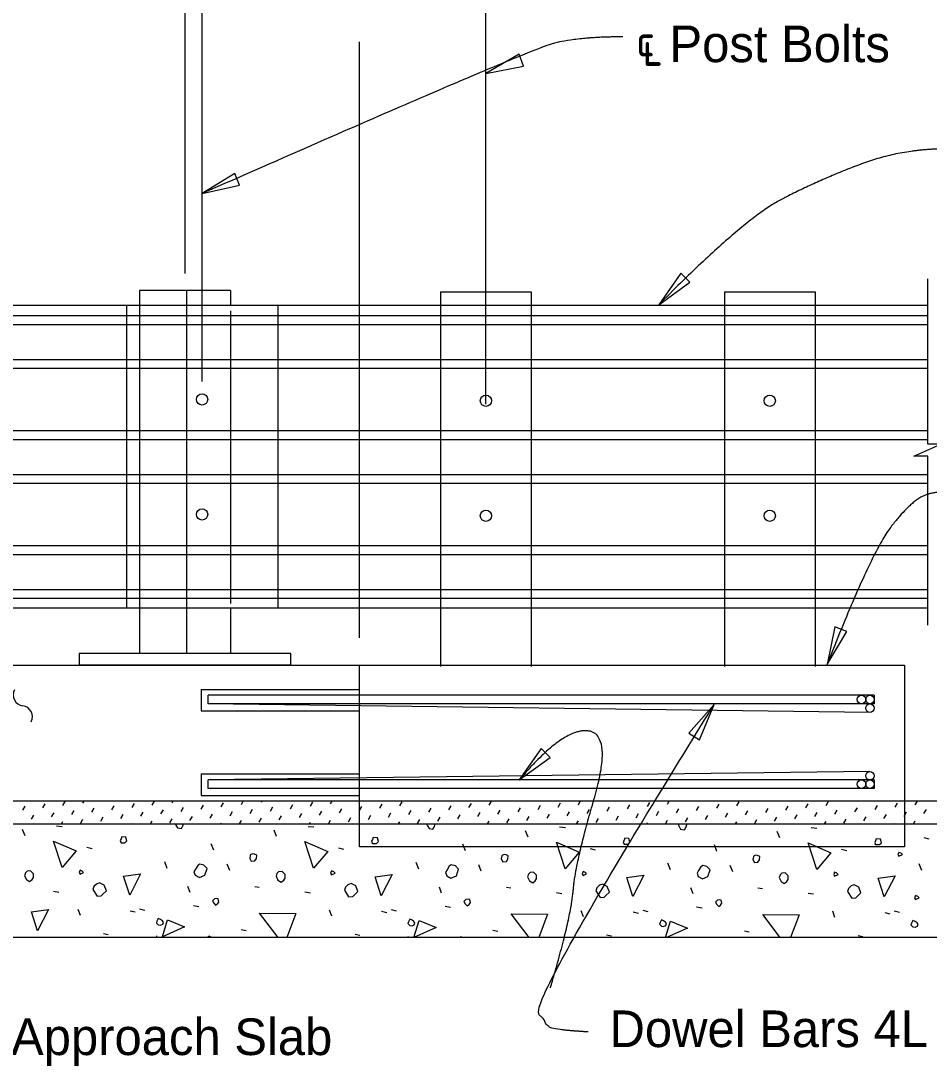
# Model space of a CAD drawing. Extents: x 0 to 41.1, y 0 to 25.9.
# Drawn here: x 31.99 to 36.99, y 5.25 to 11.01 of the extents above; entities that cross this region are included whole.
import ezdxf

# ---------------------------------------------------------------- set-up
doc = ezdxf.new("R2010")
doc.units = 0
for name, color, linetype in [('Dimension', 7, 'Continuous'), ('ExistSuperStruct', 7, 'Continuous'), ('Miscellaneous', 7, 'Continuous'), ('Rebar', 7, 'Continuous'), ('SteelMisc', 7, 'Continuous'), ('SteelMisc_h', 7, 'Continuous'), ('SubStrConc', 7, 'Continuous'), ('SubStrConc_h', 7, 'Continuous'), ('TextStructures', 7, 'Continuous')]:
    doc.layers.add(name, color=color, linetype=linetype)

msp = doc.modelspace()

# ---------------------------------------------------------------- linework, layer by layer
at = {"layer": 'Dimension'}
msp.add_line((33.8558, 7.6097), (33.8558, 10.8914), dxfattribs=at)
for points in [[(34.5515, 10.7168), (34.7588, 10.7573), (34.7339, 10.8233)], [(32.989, 10.0554), (33.1953, 10.1006), (33.1689, 10.1661)], [(35.5032, 9.4435), (35.6748, 9.5667), (35.6246, 9.6163)], [(36.43, 7.4629), (36.5385, 7.6441), (36.4727, 7.6697)], [(35.8076, 7.2429), (35.668, 7.0845), (35.7279, 7.0473)], [(34.7347, 6.8272), (34.9058, 6.9511), (34.8554, 7.0005)]]:
    msp.add_lwpolyline(points, close=True, dxfattribs=at)
msp.add_lwpolyline([(36.9839, 7.6788), (36.9839, 8.6104), (36.9064, 8.6104), (37.0564, 8.6766), (36.9839, 8.6766), (36.9839, 9.5855)], dxfattribs=at)
for centre, start, end in [((32.0093, 7.2949), 151.52667, 263.25389), ((31.9952, 7.1765), 331.52667, 83.25389)]:
    msp.add_arc(centre, 0.0596, start, end, dxfattribs=at)
for points in [[(35.3048, 10.9179), (35.0595, 10.9179), (34.7744, 10.8416), (32.989, 10.0554)], [(37.0881, 10.3011), (36.8373, 10.3011), (36.3859, 10.1306), (35.9697, 9.9149), (35.5032, 9.4435)], [(37.2746, 8.4245), (37.0591, 8.4245), (36.8965, 8.3714), (36.6668, 8.0709), (36.43, 7.4629)], [(35.1149, 5.4399), (34.9417, 5.4505), (34.8781, 5.4752), (34.8109, 5.6343), (35.8076, 7.2429)], [(34.9069, 5.6836), (35.0194, 6.0656), (35.045, 6.3745), (35.2517, 7.0806), (34.9766, 7.1138), (34.7347, 6.8272)]]:
    msp.add_open_spline(points, degree=2, dxfattribs=at)
at = {"layer": 'ExistSuperStruct'}
for p, q in [((26.6139, 7.4599), (34.561, 7.4599)), ((32.9842, 7.3261), (33.8562, 7.3261)), ((32.9842, 7.3261), (32.9842, 7.2083)), ((32.9842, 7.2083), (33.8562, 7.2083)), ((32.9842, 6.8601), (33.8562, 6.8601)), ((32.9842, 6.8601), (32.9842, 6.7423)), ((32.9842, 6.7423), (33.8562, 6.7423)), ((37.3622, 6.71), (26.6139, 6.71)), ((26.6139, 6.585), (37.3622, 6.585)), ((37.3622, 5.9599), (31.8338, 5.9599))]:
    msp.add_line(p, q, dxfattribs=at)
at = {"layer": 'Miscellaneous'}
for p, q in [((32.989, 9.0213), (32.989, 14.0792)), ((32.8952, 9.6154), (32.8952, 11.9805)), ((34.5515, 8.8961), (34.5515, 11.264)), ((34.3015, 9.5149), (34.3015, 7.4525)), ((34.3015, 9.5149), (34.8015, 9.5149)), ((34.8015, 9.5149), (34.8015, 7.4525)), ((35.864, 9.5149), (35.864, 7.4525)), ((35.864, 9.5149), (36.364, 9.5149)), ((36.364, 9.5149), (36.364, 7.4525)), ((32.5722, 9.4391), (32.5722, 7.7725)), ((33.4055, 9.4391), (33.4055, 7.7725)), ((32.5722, 9.3835), (36.9839, 9.3835)), ((32.5722, 9.3352), (36.9839, 9.3352)), ((32.5722, 9.1424), (36.9839, 9.1424)), ((32.5722, 9.0942), (36.9839, 9.0942)), ((32.5722, 8.7502), (36.9839, 8.7502)), ((32.5722, 8.702), (36.9839, 8.702)), ((32.5722, 8.5092), (36.9839, 8.5092)), ((32.5722, 8.4611), (36.9839, 8.4611)), ((32.5722, 8.1171), (36.9839, 8.1171)), ((32.5722, 8.0689), (36.9839, 8.0689)), ((32.5722, 7.8761), (36.9839, 7.8761)), ((32.5722, 7.8278), (36.9839, 7.8278)), ((32.0015, 6.6601), (32.0144, 6.6825)), ((32.1121, 6.6731), (32.1251, 6.6955)), ((32.2227, 6.686), (32.2357, 6.7084)), ((32.3334, 6.699), (32.3398, 6.71)), ((32.4928, 6.6631), (32.5058, 6.6855)), ((32.6035, 6.6761), (32.6164, 6.6985)), ((32.7141, 6.689), (32.7263, 6.71)), ((32.8247, 6.702), (32.8294, 6.71)), ((32.8736, 6.6532), (32.8865, 6.6756)), ((32.9842, 6.6661), (32.9972, 6.6885)), ((33.0948, 6.6791), (33.1078, 6.7015)), ((33.2055, 6.6921), (33.2159, 6.71)), ((33.3161, 6.705), (33.319, 6.71)), ((33.3649, 6.6562), (33.3779, 6.6786)), ((33.4756, 6.6692), (33.4885, 6.6916)), ((33.5862, 6.6821), (33.5992, 6.7045)), ((33.6968, 6.6951), (33.7055, 6.71)), ((33.8075, 6.7081), (33.8086, 6.71)), ((33.8563, 6.6592), (33.8693, 6.6816)), ((33.9669, 6.6722), (33.9799, 6.6946)), ((34.0776, 6.6851), (34.0905, 6.7075)), ((34.3477, 6.6622), (34.3606, 6.6846)), ((34.4583, 6.6752), (34.4713, 6.6976)), ((34.5689, 6.6882), (34.5816, 6.71)), ((34.7284, 6.6523), (34.7414, 6.6747)), ((34.839, 6.6653), (34.852, 6.6876)), ((34.9497, 6.6782), (34.9626, 6.7006)), ((35.0603, 6.6912), (35.0712, 6.71)), ((35.2198, 6.6553), (35.2327, 6.6777)), ((35.3304, 6.6683), (35.3434, 6.6907)), ((35.441, 6.6812), (35.454, 6.7036)), ((35.5517, 6.6942), (35.5608, 6.71)), ((35.7111, 6.6583), (35.7241, 6.6807)), ((35.8218, 6.6713), (35.8347, 6.6937)), ((35.9324, 6.6843), (35.9454, 6.7067)), ((36.2025, 6.6614), (36.2155, 6.6837)), ((36.3131, 6.6743), (36.3261, 6.6967)), ((36.4238, 6.6873), (36.4367, 6.7097)), ((36.6939, 6.6644), (36.7068, 6.6868)), ((36.8045, 6.6773), (36.8175, 6.6997)), ((36.9151, 6.6903), (36.9266, 6.71)), ((32.0503, 6.6113), (32.0633, 6.6337)), ((32.1609, 6.6242), (32.1739, 6.6466)), ((32.2716, 6.6372), (32.2845, 6.6596)), ((32.3822, 6.6502), (32.3952, 6.6725)), ((32.431, 6.6013), (32.444, 6.6237)), ((32.5417, 6.6143), (32.5546, 6.6367)), ((32.6523, 6.6272), (32.6653, 6.6496)), ((32.7629, 6.6402), (32.7759, 6.6626)), ((32.9224, 6.6043), (32.9354, 6.6267)), ((33.033, 6.6173), (33.046, 6.6397)), ((33.1437, 6.6303), (33.1566, 6.6527)), ((33.2543, 6.6432), (33.2673, 6.6656)), ((33.3031, 6.5944), (33.3161, 6.6168)), ((33.4138, 6.6074), (33.4267, 6.6298)), ((33.5244, 6.6203), (33.5374, 6.6427)), ((33.635, 6.6333), (33.648, 6.6557)), ((33.7457, 6.6463), (33.7586, 6.6686)), ((33.7945, 6.5974), (33.8075, 6.6198)), ((33.9051, 6.6104), (33.9181, 6.6328)), ((34.0158, 6.6233), (34.0287, 6.6457)), ((34.1264, 6.6363), (34.1394, 6.6587)), ((34.237, 6.6493), (34.25, 6.6717)), ((34.2859, 6.6004), (34.2988, 6.6228)), ((34.3965, 6.6134), (34.4095, 6.6358)), ((34.5071, 6.6264), (34.5201, 6.6488)), ((34.6178, 6.6393), (34.6307, 6.6617)), ((34.7772, 6.6035), (34.7902, 6.6258)), ((34.8879, 6.6164), (34.9008, 6.6388)), ((34.9985, 6.6294), (35.0115, 6.6518)), ((35.1091, 6.6423), (35.1221, 6.6647)), ((35.2686, 6.6065), (35.2816, 6.6289)), ((35.3792, 6.6194), (35.3922, 6.6418)), ((35.4899, 6.6324), (35.5028, 6.6548)), ((35.6005, 6.6454), (35.6135, 6.6678)), ((35.6493, 6.5965), (35.6623, 6.6189)), ((35.76, 6.6095), (35.7729, 6.6319)), ((35.8706, 6.6225), (35.8836, 6.6449)), ((35.9812, 6.6354), (35.9942, 6.6578)), ((36.0919, 6.6484), (36.1048, 6.6708)), ((36.1407, 6.5996), (36.1537, 6.6219)), ((36.2513, 6.6125), (36.2643, 6.6349)), ((36.362, 6.6255), (36.3749, 6.6479)), ((36.4726, 6.6384), (36.4856, 6.6608)), ((36.5832, 6.6514), (36.5962, 6.6738)), ((36.6321, 6.6026), (36.645, 6.625)), ((36.7427, 6.6155), (36.7557, 6.6379)), ((36.8533, 6.6285), (36.8663, 6.6509)), ((36.963, 6.6428), (36.976, 6.6652)), ((32.1875, 6.5755), (32.2193, 6.5719)), ((32.2153, 6.585), (32.2227, 6.5978)), ((32.3204, 6.5884), (32.3334, 6.6108)), ((32.6018, 6.585), (32.6035, 6.5878)), ((32.7049, 6.585), (32.7141, 6.6008)), ((32.8118, 6.5914), (32.8247, 6.6138)), ((33.0914, 6.585), (33.0948, 6.5909)), ((33.1946, 6.585), (33.2055, 6.6038)), ((33.5722, 6.5719), (33.604, 6.5684)), ((33.581, 6.585), (33.5862, 6.5939)), ((33.6842, 6.585), (33.6968, 6.6068)), ((34.0707, 6.585), (34.0776, 6.5969)), ((34.1752, 6.5875), (34.1882, 6.6099)), ((34.4572, 6.585), (34.4583, 6.587)), ((34.5603, 6.585), (34.5689, 6.5999)), ((34.6666, 6.5905), (34.6796, 6.6129)), ((34.9468, 6.585), (34.9497, 6.59)), ((34.9569, 6.5684), (34.9887, 6.5649)), ((35.0499, 6.585), (35.0603, 6.6029)), ((35.158, 6.5935), (35.1709, 6.6159)), ((35.4364, 6.585), (35.441, 6.593)), ((35.5395, 6.585), (35.5517, 6.606)), ((35.926, 6.585), (35.9324, 6.596)), ((36.0301, 6.5866), (36.043, 6.609)), ((36.3125, 6.585), (36.3131, 6.5861)), ((36.3416, 6.5649), (36.3734, 6.5613)), ((36.4156, 6.585), (36.4238, 6.599)), ((36.5214, 6.5896), (36.5344, 6.612)), ((36.8021, 6.585), (36.8045, 6.5891)), ((36.9052, 6.585), (36.9151, 6.6021)), ((32.0149, 6.5195), (32.0008, 6.5549)), ((33.3996, 6.516), (33.3854, 6.5513)), ((34.7843, 6.5124), (34.7701, 6.5478)), ((36.1689, 6.5089), (36.1548, 6.5443)), ((36.9615, 6.5097), (36.9898, 6.5026)), ((32.3555, 6.457), (32.3837, 6.4499)), ((33.0537, 6.4411), (33.0396, 6.4765)), ((33.7401, 6.4535), (33.7684, 6.4464)), ((34.4384, 6.4376), (34.4243, 6.4729)), ((35.1248, 6.4499), (35.1531, 6.4429)), ((35.8231, 6.434), (35.8089, 6.4694)), ((36.5095, 6.4464), (36.5378, 6.4393)), ((32.7974, 6.3403), (32.7833, 6.3757)), ((33.1415, 6.3286), (33.1274, 6.364)), ((34.1821, 6.3368), (34.1679, 6.3722)), ((34.5262, 6.3251), (34.512, 6.3604)), ((35.5668, 6.3333), (35.5526, 6.3686)), ((35.9109, 6.3215), (35.8967, 6.3569)), ((36.9514, 6.3297), (36.9373, 6.3651)), ((32.1705, 6.2155), (32.2005, 6.2102)), ((32.9229, 6.2078), (32.9105, 6.2414)), ((33.2794, 6.2402), (33.3041, 6.2367)), ((34.3076, 6.2042), (34.2952, 6.2378)), ((34.6641, 6.2367), (34.6888, 6.2331)), ((35.6923, 6.2007), (35.6799, 6.2343)), ((36.0487, 6.2331), (36.0735, 6.2296)), ((33.5552, 6.2119), (33.5852, 6.2066)), ((34.9398, 6.2084), (34.9699, 6.2031)), ((36.3245, 6.2049), (36.3546, 6.1996)), ((32.319, 6.0811), (32.3066, 6.1147)), ((32.593, 6.1076), (32.6213, 6.1006)), ((32.6454, 6.1176), (32.6737, 6.1105)), ((32.9417, 6.1359), (32.9718, 6.1306)), ((33.7036, 6.0776), (33.6913, 6.1112)), ((33.9776, 6.1041), (34.0059, 6.097)), ((34.0301, 6.1141), (34.0583, 6.107)), ((34.3264, 6.1324), (34.3565, 6.1271)), ((35.0883, 6.074), (35.0759, 6.1076)), ((35.3623, 6.1006), (35.3906, 6.0935)), ((35.4147, 6.1105), (35.443, 6.1035)), ((35.7111, 6.1288), (35.7411, 6.1235)), ((36.473, 6.0705), (36.4606, 6.1041)), ((36.7994, 6.107), (36.8277, 6.0999)), ((36.747, 6.097), (36.7753, 6.09)), ((33.2051, 6.0033), (33.2317, 5.998)), ((34.5898, 5.9998), (34.6163, 5.9945)), ((35.9745, 5.9963), (36.001, 5.991)), ((32.4462, 5.9821), (32.4728, 5.9768)), ((32.7423, 5.9599), (32.7391, 5.9686)), ((33.8309, 5.9786), (33.8574, 5.9733)), ((34.1256, 5.9599), (34.1237, 5.9651)), ((35.2156, 5.975), (35.2421, 5.9697)), ((35.509, 5.9599), (35.5084, 5.9615)), ((36.6003, 5.9715), (36.6268, 5.9662))]:
    msp.add_line(p, q, dxfattribs=at)
for points in [[(32.8422, 6.585), (32.8451, 6.579)], [(32.8451, 6.579), (32.854, 6.5631), (32.8752, 6.5596), (32.884, 6.5755), (32.8864, 6.585)], [(34.2271, 6.585), (34.2263, 6.5825), (34.2298, 6.5755)], [(34.2298, 6.5755), (34.2387, 6.5596), (34.2599, 6.556), (34.2687, 6.5719), (34.272, 6.585)], [(35.6129, 6.585), (35.611, 6.579), (35.6145, 6.5719)], [(35.6145, 6.5719), (35.6233, 6.556), (35.6445, 6.5525), (35.6534, 6.5684), (35.6569, 6.5825), (35.6545, 6.585)], [(32.5428, 6.4818), (32.5641, 6.4818), (32.5747, 6.4924), (32.5694, 6.5118), (32.5464, 6.5136), (32.5428, 6.503), (32.5375, 6.4941), (32.5428, 6.4818), (32.5393, 6.4853)], [(33.9275, 6.4782), (33.9487, 6.4782), (33.9593, 6.4888), (33.954, 6.5083), (33.9311, 6.5101), (33.9275, 6.4994), (33.9222, 6.4906), (33.9275, 6.4782), (33.924, 6.4818)], [(35.3122, 6.4747), (35.3334, 6.4747), (35.344, 6.4853), (35.3387, 6.5047), (35.3157, 6.5065), (35.3122, 6.4959), (35.3069, 6.4871), (35.3122, 6.4747), (35.3087, 6.4782)], [(36.6969, 6.4712), (36.7181, 6.4712), (36.7287, 6.4818), (36.7234, 6.5012), (36.7004, 6.503), (36.6969, 6.4924), (36.6916, 6.4835), (36.6969, 6.4712), (36.6933, 6.4747)], [(32.2182, 6.3445), (32.1705, 6.4912), (32.296, 6.4364), (32.2182, 6.3445)], [(33.6029, 6.341), (33.5552, 6.4877), (33.6807, 6.4329), (33.6029, 6.341)], [(34.9876, 6.3374), (34.9398, 6.4842), (35.0653, 6.4294), (34.9876, 6.3374)], [(36.3722, 6.3339), (36.3245, 6.4806), (36.45, 6.4258), (36.3722, 6.3339)], [(33.2511, 6.3958), (33.2599, 6.3799), (33.2794, 6.3816), (33.2882, 6.394), (33.29, 6.4135), (33.2776, 6.4188), (33.2688, 6.4205), (33.2582, 6.417), (33.2546, 6.4135), (33.2511, 6.3958)], [(34.6358, 6.3922), (34.6446, 6.3763), (34.6641, 6.3781), (34.6729, 6.3905), (34.6747, 6.4099), (34.6623, 6.4152), (34.6535, 6.417), (34.6428, 6.4135), (34.6393, 6.4099), (34.6358, 6.3922)], [(36.0205, 6.3887), (36.0293, 6.3728), (36.0487, 6.3746), (36.0576, 6.3869), (36.0593, 6.4064), (36.047, 6.4117), (36.0381, 6.4135), (36.0275, 6.4099), (36.024, 6.4064), (36.0205, 6.3887)], [(36.8244, 6.4075), (36.8438, 6.4163), (36.8367, 6.4234), (36.8244, 6.4287), (36.8191, 6.4163), (36.8244, 6.4075)], [(32.3172, 6.3092), (32.3366, 6.318), (32.3296, 6.3251), (32.3172, 6.3304), (32.3119, 6.318), (32.3172, 6.3092)], [(32.9512, 6.3032), (32.9742, 6.2909), (33.0042, 6.3032), (33.0166, 6.3403), (32.9989, 6.358), (32.976, 6.3633), (32.9653, 6.3563), (32.953, 6.3368), (32.9441, 6.3209), (32.9512, 6.3032)], [(34.3359, 6.2997), (34.3589, 6.2873), (34.3889, 6.2997), (34.4013, 6.3368), (34.3836, 6.3545), (34.3606, 6.3598), (34.35, 6.3527), (34.3376, 6.3333), (34.3288, 6.3174), (34.3359, 6.2997)], [(35.7206, 6.2962), (35.7435, 6.2838), (35.7736, 6.2962), (35.786, 6.3333), (35.7683, 6.351), (35.7453, 6.3563), (35.7347, 6.3492), (35.7223, 6.3297), (35.7135, 6.3138), (35.7206, 6.2962)], [(32.0114, 6.3003), (32.022, 6.2791), (32.0397, 6.2685), (32.0538, 6.2791), (32.0609, 6.2897), (32.0609, 6.3109), (32.045, 6.3268), (32.0255, 6.3251), (32.0167, 6.3162), (32.0114, 6.3003)], [(32.5906, 6.1936), (32.557, 6.2979), (32.6507, 6.3103), (32.5906, 6.1936)], [(33.3961, 6.2968), (33.4067, 6.2756), (33.4243, 6.265), (33.4385, 6.2756), (33.4456, 6.2862), (33.4456, 6.3074), (33.4296, 6.3233), (33.4102, 6.3215), (33.4014, 6.3127), (33.3961, 6.2968)], [(33.7019, 6.3056), (33.7213, 6.3145), (33.7143, 6.3215), (33.7019, 6.3268), (33.6966, 6.3145), (33.7019, 6.3056)], [(33.9753, 6.1901), (33.9417, 6.2944), (34.0354, 6.3068), (33.9753, 6.1901)], [(34.7807, 6.2932), (34.7913, 6.272), (34.809, 6.2614), (34.8232, 6.272), (34.8302, 6.2826), (34.8302, 6.3039), (34.8143, 6.3198), (34.7949, 6.318), (34.786, 6.3092), (34.7807, 6.2932)], [(35.0866, 6.3021), (35.106, 6.3109), (35.0989, 6.318), (35.0866, 6.3233), (35.0813, 6.3109), (35.0866, 6.3021)], [(35.3599, 6.1866), (35.3263, 6.2909), (35.42, 6.3032), (35.3599, 6.1866)], [(36.1654, 6.2897), (36.176, 6.2685), (36.1937, 6.2579), (36.2078, 6.2685), (36.2149, 6.2791), (36.2149, 6.3003), (36.199, 6.3162), (36.1796, 6.3145), (36.1707, 6.3056), (36.1654, 6.2897)], [(36.4712, 6.2985), (36.4907, 6.3074), (36.4836, 6.3145), (36.4712, 6.3198), (36.4659, 6.3074), (36.4712, 6.2985)], [(36.7446, 6.183), (36.711, 6.2873), (36.8047, 6.2997), (36.7446, 6.183)], [(32.3879, 6.2243), (32.4109, 6.1872), (32.4339, 6.1889), (32.4427, 6.1978), (32.4622, 6.2172), (32.4498, 6.2473), (32.425, 6.2614), (32.4074, 6.2544), (32.3932, 6.2402), (32.3879, 6.2243)], [(33.7726, 6.2208), (33.7956, 6.1836), (33.8186, 6.1854), (33.8274, 6.1942), (33.8468, 6.2137), (33.8345, 6.2437), (33.8097, 6.2579), (33.792, 6.2508), (33.7779, 6.2367), (33.7726, 6.2208)], [(35.1573, 6.2172), (35.1802, 6.1801), (35.2032, 6.1819), (35.2121, 6.1907), (35.2315, 6.2102), (35.2191, 6.2402), (35.1944, 6.2544), (35.1767, 6.2473), (35.1626, 6.2331), (35.1573, 6.2172)], [(36.5419, 6.2137), (36.5649, 6.1766), (36.5879, 6.1783), (36.5967, 6.1872), (36.6162, 6.2066), (36.6038, 6.2367), (36.5791, 6.2508), (36.5614, 6.2437), (36.5472, 6.2296), (36.5419, 6.2137)], [(33.0531, 6.1483), (33.0637, 6.1377), (33.0743, 6.1448), (33.0814, 6.1554), (33.0779, 6.173), (33.069, 6.1748), (33.0566, 6.173), (33.046, 6.1624), (33.0531, 6.1483)], [(34.4378, 6.1448), (34.4484, 6.1341), (34.459, 6.1412), (34.4661, 6.1518), (34.4625, 6.1695), (34.4537, 6.1713), (34.4413, 6.1695), (34.4307, 6.1589), (34.4378, 6.1448)], [(35.8225, 6.1412), (35.8331, 6.1306), (35.8437, 6.1377), (35.8507, 6.1483), (35.8472, 6.166), (35.8384, 6.1677), (35.826, 6.166), (35.8154, 6.1554), (35.8225, 6.1412)], [(36.9168, 6.1698), (36.9362, 6.1786), (36.9292, 6.1857), (36.9168, 6.191), (36.9115, 6.1786), (36.9168, 6.1698)], [(32.0837, 5.9974), (32.0502, 6.1017), (32.1439, 6.1141), (32.0837, 5.9974)], [(32.7479, 6.0292), (32.7603, 6.0275), (32.7727, 6.0328), (32.7762, 6.0434), (32.7709, 6.0522), (32.7603, 6.0593), (32.7479, 6.0646), (32.7408, 6.0504), (32.7373, 6.0398), (32.7479, 6.0292)], [(32.7703, 5.9644), (32.7985, 6.0564), (32.8922, 6.0192), (32.7703, 5.9644)], [(33.4074, 5.9599), (33.3059, 6.0935), (33.5057, 6.0917), (33.4564, 5.9599)], [(34.1326, 6.0257), (34.145, 6.0239), (34.1573, 6.0292), (34.1609, 6.0398), (34.1556, 6.0487), (34.145, 6.0557), (34.1326, 6.061), (34.1255, 6.0469), (34.122, 6.0363), (34.1326, 6.0257)], [(34.1549, 5.9609), (34.1832, 6.0528), (34.2769, 6.0157), (34.1549, 5.9609)], [(34.7894, 5.9599), (34.6906, 6.09), (34.8903, 6.0882), (34.8424, 5.9599)], [(35.5173, 6.0221), (35.5296, 6.0204), (35.542, 6.0257), (35.5455, 6.0363), (35.5402, 6.0451), (35.5296, 6.0522), (35.5173, 6.0575), (35.5102, 6.0434), (35.5067, 6.0328), (35.5173, 6.0221)], [(35.5404, 5.9599), (35.5679, 6.0493), (35.6616, 6.0122), (35.5453, 5.9599)], [(36.1714, 5.9599), (36.0753, 6.0864), (36.275, 6.0846), (36.2284, 5.9599)], [(36.9019, 6.0186), (36.9143, 6.0168), (36.9267, 6.0221), (36.9302, 6.0328), (36.9249, 6.0416), (36.9143, 6.0487), (36.9019, 6.054), (36.8949, 6.0398), (36.8913, 6.0292), (36.9019, 6.0186)], [(33.0427, 5.9599), (33.0425, 5.9609), (33.0284, 5.968), (33.0149, 5.9599)], [(34.4221, 5.9599), (34.413, 5.9644), (34.4055, 5.9599)], [(35.7996, 5.9599), (35.7977, 5.9609), (35.7961, 5.9599)]]:
    msp.add_lwpolyline(points, dxfattribs=at)
at = {"layer": 'Rebar'}
for p, q in [((36.6891, 7.2933), (33.0225, 7.2933)), ((33.0225, 7.2464), (33.0225, 7.2933)), ((36.6891, 7.2933), (36.6891, 7.2464)), ((36.6891, 7.2464), (33.0225, 7.2464)), ((36.6657, 7.1995), (33.0225, 7.2464)), ((36.6657, 6.8741), (33.0225, 6.8272)), ((36.6891, 6.8272), (33.0225, 6.8272)), ((33.0225, 6.7804), (33.0225, 6.8272)), ((36.6891, 6.8272), (36.6891, 6.7804)), ((36.6891, 6.7804), (33.0225, 6.7804))]:
    msp.add_line(p, q, dxfattribs=at)
for centre in [(36.6188, 7.2698), (36.6657, 7.2698), (36.6657, 7.2229), (36.6657, 6.8507), (36.6188, 6.8038), (36.6657, 6.8038)]:
    msp.add_circle(centre, 0.0234, dxfattribs=at)
at = {"layer": 'SteelMisc'}
for p, q in [((33.1452, 9.5225), (32.6452, 9.5225)), ((32.6452, 9.5225), (32.6452, 9.4391)), ((33.1452, 9.5225), (33.1452, 9.4391)), ((32.5722, 9.4391), (20.3176, 9.4391)), ((20.3176, 9.3835), (32.5722, 9.3835)), ((20.3176, 9.3353), (32.5722, 9.3353)), ((20.3176, 9.1425), (32.5722, 9.1425)), ((20.3176, 9.0943), (32.5722, 9.0943)), ((20.3176, 8.7503), (32.5722, 8.7503)), ((20.3176, 8.7021), (32.5722, 8.7021)), ((20.3176, 8.5093), (32.5722, 8.5093)), ((20.3176, 8.4611), (32.5722, 8.4611)), ((20.3176, 8.1172), (32.5722, 8.1172)), ((20.3176, 8.069), (32.5722, 8.069)), ((20.3176, 7.8761), (32.5722, 7.8761)), ((20.3176, 7.8279), (32.5722, 7.8279)), ((32.5722, 7.7724), (20.3176, 7.7724)), ((32.6452, 7.7724), (32.6452, 7.5225)), ((33.1452, 7.7725), (33.1452, 7.5225)), ((33.4785, 7.5225), (32.3119, 7.5225)), ((32.3119, 7.5225), (32.3119, 7.46)), ((33.1452, 7.5225), (32.6452, 7.5225)), ((33.4785, 7.46), (33.4785, 7.5225)), ((33.4785, 7.46), (32.3119, 7.46))]:
    msp.add_line(p, q, dxfattribs=at)
for centre in [(32.989, 8.9224), (32.989, 8.2892)]:
    msp.add_circle(centre, 0.0312, dxfattribs=at)
at = {"layer": 'SteelMisc_h'}
for p, q in [((32.9056, 7.5225), (32.9056, 9.5225)), ((36.9839, 9.439), (32.5722, 9.439)), ((32.6452, 9.439), (32.6452, 7.7724)), ((33.1452, 9.4106), (33.1452, 7.7987)), ((36.9839, 7.7723), (32.5722, 7.7723))]:
    msp.add_line(p, q, dxfattribs=at)
for centre in [(34.5515, 8.9148), (36.114, 8.9148), (34.5515, 8.2817), (36.114, 8.2817)]:
    msp.add_circle(centre, 0.0312, dxfattribs=at)
at = {"layer": 'SubStrConc'}
for p, q in [((33.8558, 6.7099), (33.8558, 7.4599)), ((33.8558, 7.4599), (36.8558, 7.4599)), ((36.8558, 7.4599), (36.8558, 6.7099))]:
    msp.add_line(p, q, dxfattribs=at)
at = {"layer": 'SubStrConc_h'}
msp.add_lwpolyline([(36.8558, 6.7099), (36.8558, 6.4599), (33.8558, 6.4599), (33.8558, 6.7099)], dxfattribs=at)

# ---------------------------------------------------------------- texts
at = {"layer": 'Dimension'}
msp.add_text('Dowel Bars 4L (10" Embedment) ', height=0.2016, dxfattribs=at).set_placement((35.2319, 5.3567))
at = {"layer": 'TextStructures'}
for s, p in [('℄ Post Bolts', (35.3777, 10.7786)), ('Existing Approach Slab', (30.9186, 5.3129))]:
    msp.add_text(s, height=0.2016, dxfattribs=at).set_placement(p)

doc.saveas('drawing.dxf')
